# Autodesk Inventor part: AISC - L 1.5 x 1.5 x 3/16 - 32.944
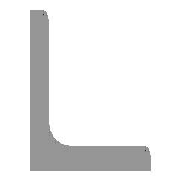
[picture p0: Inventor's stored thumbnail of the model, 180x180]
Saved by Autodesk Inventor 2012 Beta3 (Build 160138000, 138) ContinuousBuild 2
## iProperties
IsCustomPart: 1
Created: 2010-11
Part Number: AISC - L 1.5 x 1.5 x 3/16 - 32.944
Material: Steel, Mild
Description: Angle Steel
Document SubType Name: Modeling
Standard: ANSI
Designer: Beta-8540w
Standards Organization: ANSI
Language: en-US
Size Designation: L 1.5 x 1.5 x 3/16
Categories: <MemberInstance><Categories><Category DisplayName="Structural Shapes" InternalName="089c4875-fa83-4c05-b084-43b9cc11f5ed" Mnemonic="GRDR"><CategoryParameter Dis
Stock Number: L 1.5 x 1.5 x 3/16
Density: 7.86 g/cm^3
_CCFamilyMember: 5
_CCFamilyDisplayName: ANSI L (Equal angles) - Angle Steel
_FrameMemberDoc: Frame Member File
_Version: 15.0.0
_GetPNFromCC: 1
G_L: 32.944 in
G_W: 1.500 in
G_H: 1.500 in
Author: Beta-8540w
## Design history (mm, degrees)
node "Start plane"
node "End plane"
sketch "Sketch"
  geometry: L1 (38.1, 0)-(0, 0); L2 (0, 0)-(0, 38.1); L3 (0, 38.1)-(2.476, 38.1); L4 (4.762, 35.814)-(4.762, 9.589); L5 (9.588, 4.763)-(35.814, 4.763); L6 (38.1, 2.477)-(38.1, 0); L7 (0, -11.041)-(0, 31.538); L8 (-11.041, 0)-(31.538, 0); L9 (0, 48.496)-(0, -20.964) reference; L10 (-20.964, 0)-(48.496, 0) reference; A1 r 4.826 centre (9.588, 9.589) between (4.762, 9.589) and (9.588, 4.763); A2 r 2.286 centre (2.476, 35.814) between (4.762, 35.814) and (2.476, 38.1); A3 r 2.286 centre (35.814, 2.477) between (38.1, 2.477) and (35.814, 4.763); 3 further points
  constraints: 16 end point, 6 point on circle, 6 point on line, 6 tangent, 4 parallel, 3 centre point, 2 collinear, 1 equal radius, 1 horizontal, 1 perpendicular
  dimensions: "d0" = 38.1 distance between parallel lines of L6 L2 (= G_H); "d1" = 38.1 distance between parallel lines of L3 L1 (= G_H); "d2" = 4.7625 distance between parallel lines of L2 L4 (= G_T); "d3" = 4.7625 distance between parallel lines of L1 L5 (= G_T); "d10" = 0 distance between parallel lines of L7 L2 (computed from ex); "d11" = 0 distance between parallel lines of L8 L1 (computed from d10); "d14" = 4.826 radius of A1 (= G_IR); "d15" = 2.286 radius of A2 (= G_ER)
extrude "Body" new body sketch "Sketch" stored distance "d4" = 836.76542 (= G_L); taper "d5" = 0 deg
node "Driven Length"
  sketch "Sketch3"
    geometry: L1 (0, 0)-(10, 0) reference
    constraints: 2 end point, 1 horizontal
  workplane "Work Plane3"
  sketch "Sketch4"
    geometry: L1 (-2, 0)-(12, 0) reference; L2 (-2, 836.765)-(12, 836.765) reference
    dimensions: "d17" = 836.76542 distance between parallel lines of L1 L2 (derived)
body "Solid1"
other parameters: "G_H" = 38.1 [user parameter; used in 2 equation terms], "G_T" = 4.7625 [user parameter; used in 2 equation terms], "G_ER" = 2.286 [user parameter; used in 1 equation term], "G_IR" = 4.826 [user parameter; used in 1 equation term], "G_L" = 836.76542 (= d17) [user parameter; used in 1 equation term], "ex" = 0 [user parameter; used in 1 equation term], "G_OFFSET_START" = 0 [user parameter; used in 1 equation term], "G_OFFSET_END" = 0 [user parameter; used in 1 equation term], "d12" = 0 (computed from G_OFFSET_START), "d13" = 836.76542 (= G_OFFSET_END + B_L), "B_L" = 836.76542 [user parameter; used in 1 equation term], "d16" = 90 deg, "MAS" = 0.26787 [user parameter]
